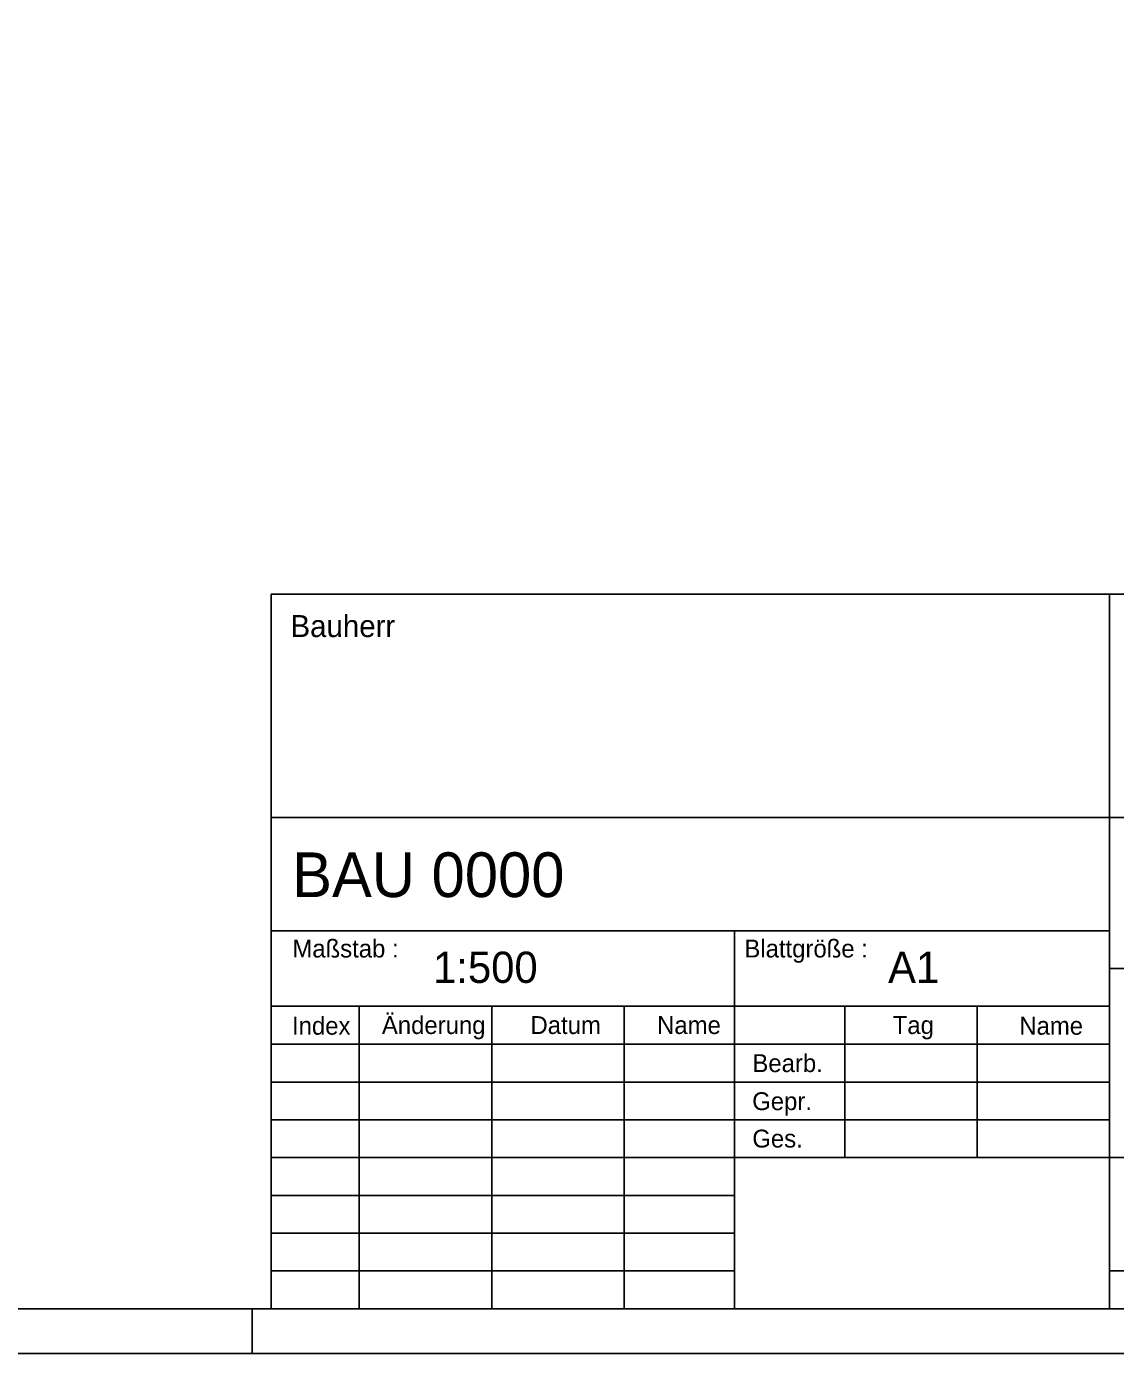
# Model space of a CAD drawing. Extents: x 0 to 420, y 0 to 297.
# Drawn here: x 315.4 to 376.3, y 0 to 74.2 of the extents above; entities that cross this region are included whole.
import ezdxf

# ---------------------------------------------------------------- set-up
doc = ezdxf.new("R2010")
doc.units = 0
doc.layers.add('90_Plankopf', color=7, linetype='Continuous')

msp = doc.modelspace()

# ---------------------------------------------------------------- linework, layer by layer
at = {"layer": '90_Plankopf'}
for p, q in [((418, 42.495), (329.06, 42.495)), ((329.06, 42.495), (329.06, 29.995)), ((376.001, 29.995), (376.001, 42.495)), ((329.06, 29.995), (418, 29.995)), ((329.06, 2.5), (329.06, 29.995)), ((329.06, 29.995), (418, 29.995)), ((376.001, 2.5), (376.001, 29.995)), ((329.06, 23.65), (376.001, 23.65)), ((355.001, 2.5), (355.001, 23.65)), ((376.001, 21.535), (418, 21.535)), ((329.06, 19.435), (376.001, 19.435)), ((334.001, 19.42), (334.001, 2.5)), ((341.413, 2.5), (341.413, 19.42)), ((348.825, 2.5), (348.825, 19.42)), ((361.177, 19.42), (361.177, 10.96)), ((368.589, 10.96), (368.589, 19.42)), ((329.06, 17.315), (376.001, 17.315)), ((329.06, 15.19), (376.001, 15.19)), ((329.06, 13.075), (376.001, 13.075)), ((329.06, 10.96), (376.001, 10.96)), ((329.06, 10.96), (376.001, 10.96)), ((355.001, 10.96), (376.001, 10.96)), ((376.001, 10.96), (418, 10.96)), ((355.001, 8.845), (329.06, 8.845)), ((355.001, 6.73), (329.06, 6.73)), ((329.06, 4.615), (355.001, 4.615)), ((376.001, 4.615), (418, 4.615)), ((328, 0), (328, 2.5)), ((418, 2.5), (329.06, 2.5)), ((329.06, 2.5), (355.001, 2.5)), ((334.9, 2.5), (418, 2.5)), ((334.9, 2.5), (418, 2.5))]:
    msp.add_line(p, q, dxfattribs=at)
for points in [[(0, 0), (420.5, 0), (420.5, 297), (0, 297)], [(12.5, 294.5), (418, 294.5), (418, 2.5), (12.5, 2.5)]]:
    msp.add_lwpolyline(points, close=True, dxfattribs=at)

# ---------------------------------------------------------------- texts
for s, height, p in [('Bauherr', 1.2318, (330.151, 40.087)), ('BAU 0000      ', 2.5, (330.245, 25.538)), ('Maßstab :', 1, (330.258, 22.158)), ('Blattgröße :', 0.99995, (355.558, 22.158)), ('1:500    ', 1.75, (338.131, 20.734)), ('A1       ', 1.75, (363.6, 20.734)), ('Index', 1, (330.235, 17.837)), ('Änderung', 1, (335.267, 17.875)), ('Datum', 1, (343.584, 17.875)), ('Name', 1, (350.673, 17.875)), ('Tag', 1, (363.862, 17.875)), ('Name', 1, (370.946, 17.837)), ('Bearb.', 1, (356.007, 15.745)), ('Gepr.', 1, (355.995, 13.615)), ('Ges.', 1, (356.002, 11.524))]:
    msp.add_text(s, height=height, dxfattribs=at).set_placement(p)

doc.saveas('drawing.dxf')
